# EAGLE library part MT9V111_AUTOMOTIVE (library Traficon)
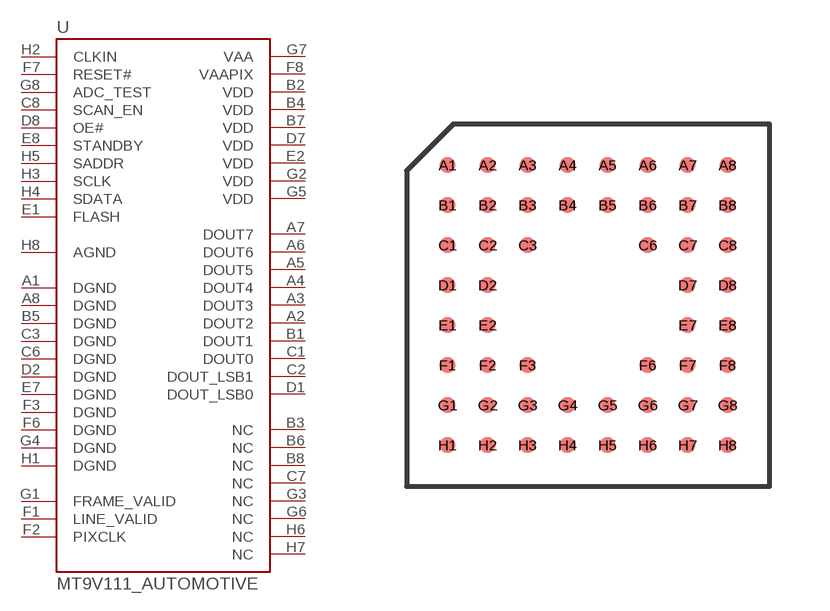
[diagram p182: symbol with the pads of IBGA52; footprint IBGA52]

Designator prefix U

## MT9V111_AUTOMOTIVE  [IBGA52]
A1  DGND  pwr
A2  DOUT2  out
A3  DOUT3  out
A4  DOUT4  out
A5  DOUT5  out
A6  DOUT6  out
A7  DOUT7  out
A8  DGND  pwr
B1  DOUT1  out
B2  VDD  pwr
B3  NC  nc
B4  VDD  pwr
B5  DGND  pwr
B6  NC  nc
B7  VDD  pwr
B8  NC  nc
C1  DOUT0  out
C2  DOUT_LSB1  out
C3  DGND  pwr
C6  DGND  pwr
C7  NC  nc
C8  SCAN_EN  in
D1  DOUT_LSB0  out
D2  DGND  pwr
D7  VDD  pwr
D8  OE#  in
E1  FLASH  out
E2  VDD  pwr
E7  DGND  pwr
E8  STANDBY  in
F1  LINE_VALID  out
F2  PIXCLK  out
F3  DGND  pwr
F6  DGND  pwr
F7  RESET#  in
F8  VAAPIX  pwr
G1  FRAME_VALID  out
G2  VDD  pwr
G3  NC  nc
G4  DGND  pwr
G5  VDD  pwr
G6  NC  nc
G7  VAA  pwr
G8  ADC_TEST  in
H1  DGND  pwr
H2  CLKIN  in
H3  SCLK  in
H4  SDATA
H5  SADDR  in
H6  NC  nc
H7  NC  nc
H8  AGND  pwr

## Footprint IBGA52 (pad centres in mm)
smd 0.4 x 0.4: A1 -3.5,3.5; A2 -2.5,3.5; A3 -1.5,3.5; A4 -0.5,3.5; A5 0.5,3.5; A6 1.5,3.5; A7 2.5,3.5; A8 3.5,3.5; B1 -3.5,2.5; B2 -2.5,2.5; B3 -1.5,2.5; B4 -0.5,2.5; B5 0.5,2.5; B6 1.5,2.5; B7 2.5,2.5; B8 3.5,2.5; C1 -3.5,1.5; C2 -2.5,1.5; C3 -1.5,1.5; C6 1.5,1.5; C7 2.5,1.5; C8 3.5,1.5; D1 -3.5,0.5; D2 -2.5,0.5; D7 2.5,0.5; D8 3.5,0.5; E1 -3.5,-0.5; E2 -2.5,-0.5; E7 2.5,-0.5; E8 3.5,-0.5; F1 -3.5,-1.5; F2 -2.5,-1.5; F3 -1.5,-1.5; F6 1.5,-1.5; F7 2.5,-1.5; F8 3.5,-1.5; G1 -3.5,-2.5; G2 -2.5,-2.5; G3 -1.5,-2.5; G4 -0.5,-2.5; G5 0.5,-2.5; G6 1.5,-2.5; G7 2.5,-2.5; G8 3.5,-2.5; H1 -3.5,-3.5; H2 -2.5,-3.5; H3 -1.5,-3.5; H4 -0.5,-3.5; H5 0.5,-3.5; H6 1.5,-3.5; H7 2.5,-3.5; H8 3.5,-3.5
